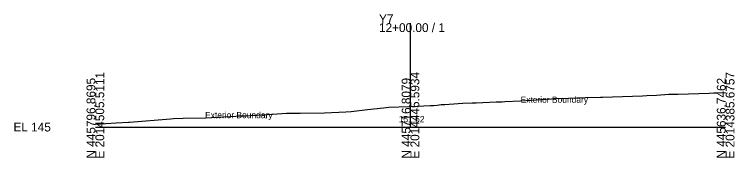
# Model space of a CAD drawing. Extents: x -26 to 203, y -10 to 7527.
# Drawn here: x -25.7 to 202.8, y 3990.3 to 4035.8 of the extents above; entities that cross this region are included whole.
import ezdxf

# ---------------------------------------------------------------- set-up
doc = ezdxf.new("R2010")
doc.units = 0
for name, color, linetype in [('Exist Cross Section Cell', 7, 'Continuous'), ('Exist XS Center Line Elevation Label', 7, 'Continuous'), ('Exist XS Ground Line', 7, 'Continuous'), ('Scratch_Level_0', 7, 'Continuous')]:
    doc.layers.add(name, color=color, linetype=linetype)

msp = doc.modelspace()

# ---------------------------------------------------------------- linework, layer by layer
at = {"layer": 'Exist Cross Section Cell'}
for p, q in [((100, 4000), (100, 4032.96)), ((0, 4000), (100, 4000)), ((100, 4000), (200, 4000))]:
    msp.add_line(p, q, dxfattribs=at)
at = {"layer": 'Exist XS Ground Line'}
msp.add_lwpolyline([(0, 4000.95), (6.56, 4001.32), (10.48, 4001.51), (10.8, 4001.53), (23.85, 4002.62), (24.81, 4002.69), (27.88, 4002.79), (35, 4002.94), (44.57, 4003.5), (46.24, 4003.58), (47.5, 4003.6), (56.2, 4004.14), (60.69, 4004.39), (61.22, 4004.4), (61.63, 4004.41), (65.02, 4004.43), (72.71, 4004.5), (79.49, 4004.88), (81.13, 4004.95), (86.4, 4005.62), (91.46, 4006.15), (93.09, 4006.32), (99.58, 4006.5), (100, 4006.52), (106.3, 4006.82), (107.34, 4006.84), (108.45, 4006.95), (109.72, 4007.14), (110.91, 4007.18), (115.17, 4007.49), (116.58, 4007.63), (119.56, 4007.67), (119.93, 4007.69), (120.79, 4007.74), (127.2, 4008.04), (129.11, 4008.02), (129.94, 4008.09), (134.94, 4008.37), (144.72, 4009.01), (146.27, 4009.12), (147.43, 4009.09), (155.5, 4009.36), (160.24, 4009.48), (160.9, 4009.51), (173.6, 4009.9), (175.03, 4009.97), (178.1, 4010.09), (181.99, 4010.46), (184.91, 4010.47), (194.79, 4010.79), (196.28, 4010.85), (197.4, 4010.85), (200, 4010.99)], dxfattribs=at)

# ---------------------------------------------------------------- texts
at = {"layer": 'Exist Cross Section Cell'}
for s, p in [('Y7', (90, 4032.96)), ('12+00.00 / 1', (90, 4030.16)), ('EL 145', (-26, 3998.6))]:
    msp.add_text(s, height=2.8, dxfattribs=at).set_placement(p)
for s, p in [('N 445796.8695', (0, 3990)), ('E 2014505.5111', (2.8, 3990)), ('N 445716.8079', (100, 3990)), ('E 2014445.5934', (102.8, 3990)), ('N 445636.7462', (200, 3990)), ('E 2014385.6757', (202.8, 3990))]:
    msp.add_text(s, height=2.8, rotation=90, dxfattribs=at).set_placement(p)
at = {"layer": 'Exist XS Center Line Elevation Label'}
msp.add_text('151.52', height=2, dxfattribs=at).set_placement((96.27, 4001.52))
at = {"layer": 'Scratch_Level_0'}
for p in [(134.93, 4007.7), (34.81, 4002.81)]:
    msp.add_text('Exterior Boundary', height=2, dxfattribs=at).set_placement(p)

doc.saveas('drawing.dxf')
